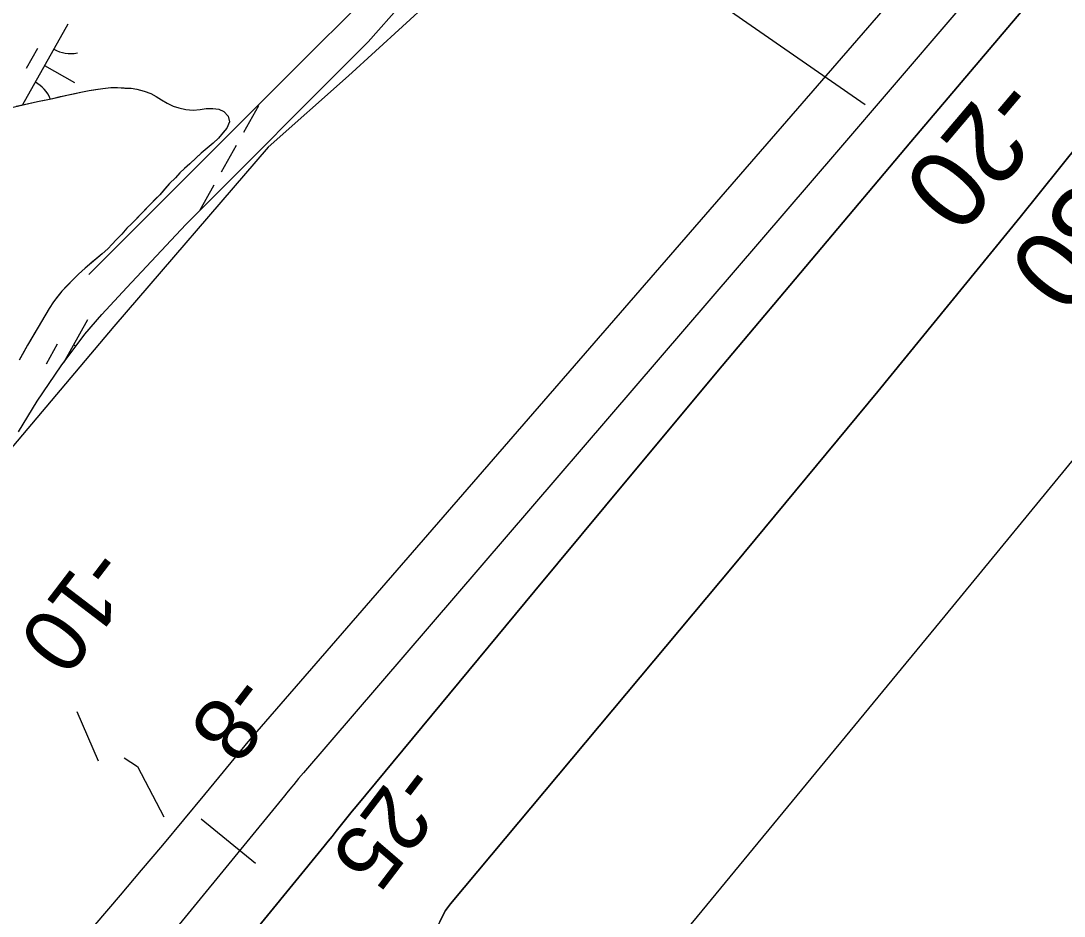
# Model space of a CAD drawing. Extents: x 3913936 to 3933962, y 195330 to 217741.
# Drawn here: x 3920751 to 3921301, y 199907 to 200379 of the extents above; entities that cross this region are included whole.
import ezdxf

# ---------------------------------------------------------------- set-up
doc = ezdxf.new("R2010")
doc.units = 0
for name, color, linetype in [('V-LEVE-TOET', 7, 'Continuous'), ('V-RIVR-EDGE', 7, 'Continuous'), ('V-RIVR-RANG', 7, 'Continuous'), ('V-RRAP-FSHR', 7, 'Continuous'), ('V-TOPO-DPTH', 7, 'Continuous'), ('V-TOPO-MINR', 7, 'Continuous'), ('V-TOPO-MINR-IDEN', 7, 'Continuous'), ('V-TOPO-SHOR', 7, 'Continuous'), ('V-WETL-SWMP', 7, 'Continuous')]:
    doc.layers.add(name, color=color, linetype=linetype)

msp = doc.modelspace()

# ---------------------------------------------------------------- linework, layer by layer
at = {"layer": 'V-LEVE-TOET'}
for p, q in [((3921120.69, 200387.67), (3921196.16, 200335.19)), ((3920780.73, 200015.29), (3920791.94, 199989.35)), ((3920846.19, 199958.71), (3920874.83, 199935.41))]:
    msp.add_line(p, q, dxfattribs=at)
msp.add_lwpolyline([(3920805.66, 199990.88), (3920812.72, 199986.44), (3920826.52, 199959.76)], dxfattribs=at)
at = {"layer": 'V-RIVR-EDGE'}
msp.add_lwpolyline([(3921670.35, 201179.41), (3921549.12, 201020.46), (3921415.83, 200875.05), (3921337.06, 200789.01), (3921188.01, 200632.69), (3921116.52, 200553.92), (3921101.97, 200528.48), (3921075.31, 200490.91), (3921049.87, 200450.92), (3921013.51, 200416.99), (3920980.8, 200402.45), (3920923.84, 200350.34), (3920881.43, 200312.78), (3920800.24, 200218.26), (3920726.32, 200131.01), (3920696.03, 200086.18), (3920643.92, 200055.88), (3920594.24, 200014.68), (3920561.69, 199977.31)], dxfattribs=at)
at = {"layer": 'V-RRAP-FSHR'}
msp.add_lwpolyline([(3921316.26, 200790.85), (3921288.87, 200761.7), (3921261.48, 200732.55), (3921234.92, 200703.4), (3921206.7, 200674.25), (3921179.24, 200645.17), (3921151.59, 200616.25), (3921123.95, 200587.34), (3921096.31, 200558.43), (3921068.67, 200529.52), (3921041.3, 200500.6), (3921013.29, 200471.79), (3920984.99, 200443.51), (3920956.7, 200415.24), (3920928.4, 200386.97), (3920900.1, 200358.7), (3920871.81, 200330.43), (3920843.51, 200302.15), (3920815.21, 200273.88), (3920786.92, 200245.61)], dxfattribs=at)
at = {"layer": 'V-TOPO-DPTH'}
for points in [[(3920788.48, 199794.34), (3920911.1, 199944.31), (3920913.22, 199946.93), (3920915.33, 199949.55), (3920917.43, 199952.19), (3920919.51, 199954.83), (3920921.59, 199957.48), (3920923.69, 199960.11), (3920925.82, 199962.73), (3920927.95, 199965.33), (3921022.08, 200078.98), (3921071.39, 200138.31), (3921120.84, 200197.54), (3921170.49, 200256.59), (3921220.27, 200315.53), (3921558.35, 200714.44)], [(3920788.48, 199794.34), (3920911.1, 199944.31), (3920913.22, 199946.93), (3920915.33, 199949.55), (3920917.43, 199952.19), (3920919.51, 199954.83), (3920921.59, 199957.48), (3920923.69, 199960.11), (3920925.82, 199962.73), (3920927.95, 199965.33), (3921022.08, 200078.98), (3921071.39, 200138.31), (3921120.84, 200197.54), (3921170.49, 200256.59), (3921220.27, 200315.53), (3921558.35, 200714.44)], [(3921471.9, 200692.25), (3920871.94, 200000.8), (3920869.85, 199998.3), (3920869.16, 199997.46), (3920847.89, 199971.56), (3920836.87, 199958.21), (3920825.8, 199944.92), (3920814.65, 199931.69), (3920803.45, 199918.5), (3920734.51, 199837.88)], [(3921352.15, 200368.45), (3921277.9, 200275.87), (3921202.76, 200184.01), (3921127.03, 200092.63), (3920977.56, 199914.02), (3920974.94, 199910.42), (3920973.84, 199908.49), (3920971.91, 199904.46), (3920970.96, 199902.43), (3920969, 199898.4), (3920967.88, 199896.34), (3920966.71, 199894.4), (3920964.02, 199890.75), (3920850.02, 199744.69)], [(3920850.02, 199744.69), (3920964.02, 199890.75), (3920966.71, 199894.4), (3920967.88, 199896.34), (3920969, 199898.4), (3920970.96, 199902.43), (3920971.91, 199904.46), (3920973.84, 199908.49), (3920974.94, 199910.42), (3920977.56, 199914.02), (3921127.03, 200092.63), (3921202.76, 200184.01), (3921277.9, 200275.87), (3921352.15, 200368.45)], [(3921311.35, 200154.93), (3921238.07, 200065.8), (3921049.22, 199836.48), (3921047.87, 199834.83), (3921045.18, 199831.52), (3921043.85, 199829.86), (3921041.19, 199826.53), (3921039.87, 199824.86), (3921038.56, 199823.18), (3920928.23, 199681.59)], [(3921311.35, 200154.93), (3921238.07, 200065.8), (3921049.22, 199836.48), (3921047.87, 199834.83), (3921045.18, 199831.52), (3921043.85, 199829.86), (3921041.19, 199826.53), (3921039.87, 199824.86), (3921038.56, 199823.18), (3920928.23, 199681.59)]]:
    msp.add_lwpolyline(points, dxfattribs=at)
at = {"layer": 'V-TOPO-MINR'}
for points in [[(3921558.35, 200714.44), (3921220.27, 200315.53), (3921170.49, 200256.59), (3921120.84, 200197.54), (3921071.39, 200138.31), (3921022.08, 200078.98), (3920927.95, 199965.33), (3920925.82, 199962.73), (3920923.69, 199960.11), (3920921.59, 199957.48), (3920919.51, 199954.83), (3920917.43, 199952.19), (3920915.33, 199949.55), (3920913.22, 199946.93), (3920911.1, 199944.31), (3920788.48, 199794.34)], [(3921471.9, 200692.25), (3920871.94, 200000.8), (3920869.85, 199998.3), (3920869.16, 199997.46), (3920847.89, 199971.56), (3920836.87, 199958.21), (3920825.8, 199944.92), (3920814.65, 199931.69), (3920803.45, 199918.5), (3920734.51, 199837.88)], [(3921302.59, 200452.29), (3921241.83, 200381.14), (3921180.96, 200310.09), (3920900.1, 199982.95), (3920897.57, 199979.97), (3920895.08, 199976.95), (3920893.84, 199975.43), (3920891.36, 199972.4), (3920890.13, 199970.89), (3920813.14, 199876.93), (3920773.5, 199828.36), (3920762.73, 199815.11)], [(3921352.15, 200368.45), (3921277.9, 200275.87), (3921202.76, 200184.01), (3921127.03, 200092.63), (3920977.56, 199914.02), (3920974.94, 199910.42), (3920973.84, 199908.49), (3920971.91, 199904.46), (3920970.96, 199902.43), (3920969, 199898.4), (3920967.88, 199896.34), (3920966.71, 199894.4), (3920964.02, 199890.75), (3920850.02, 199744.69)], [(3921311.35, 200154.93), (3921238.07, 200065.8), (3921049.22, 199836.48), (3921047.87, 199834.83), (3921045.18, 199831.52), (3921043.85, 199829.86), (3921041.19, 199826.53), (3921039.87, 199824.86), (3921038.56, 199823.18), (3920928.23, 199681.59)]]:
    msp.add_lwpolyline(points, dxfattribs=at)
at = {"layer": 'V-TOPO-SHOR'}
msp.add_lwpolyline([(3920748.67, 200334.3), (3920752.03, 200335.05), (3920756.76, 200336.06), (3920759.99, 200336.82), (3920763.6, 200337.57), (3920767.96, 200338.46), (3920772.06, 200339.46), (3920775.42, 200340.22), (3920779.77, 200341.1), (3920782.75, 200341.73), (3920787.23, 200342.62), (3920790.59, 200343.12), (3920794.45, 200343.76), (3920798.68, 200344.14), (3920802.04, 200344.15), (3920806.02, 200343.92), (3920809.26, 200343.8), (3920812.37, 200343.31), (3920816.11, 200342.2), (3920819.72, 200340.97), (3920822.47, 200339.48), (3920825.33, 200337.62), (3920828.33, 200335.89), (3920831.44, 200334.4), (3920834.43, 200333.42), (3920838.04, 200332.55), (3920842.03, 200332.32), (3920845.64, 200332.58), (3920848.87, 200333.08), (3920852.35, 200333.22), (3920855.47, 200332.73), (3920858.21, 200331.49), (3920860.46, 200329.13), (3920861.21, 200326.15), (3920859.73, 200322.78), (3920857.62, 200320.29), (3920855.26, 200317.54), (3920852.53, 200314.92), (3920849.3, 200312.17), (3920846.2, 200309.55), (3920843.84, 200307.43), (3920840.24, 200304.06), (3920837.38, 200301.56), (3920835.02, 200299.19), (3920832.67, 200296.57), (3920829.56, 200293.57), (3920826.83, 200290.58), (3920824.35, 200287.71), (3920822, 200285.34), (3920819.64, 200282.96), (3920817.4, 200280.59), (3920815.17, 200278.1), (3920811.69, 200274.61), (3920809.46, 200272.36), (3920806.98, 200270.11), (3920804.37, 200266.99), (3920801.39, 200264), (3920799.29, 200261.62), (3920796.93, 200259.26), (3920794.07, 200256.63), (3920790.84, 200253.89), (3920788.11, 200251.64), (3920785.01, 200249.02), (3920781.53, 200245.89), (3920778.55, 200242.9), (3920775.32, 200239.65), (3920772.72, 200236.91), (3920770.73, 200234.29), (3920768.38, 200231.29), (3920766.02, 200227.68), (3920763.79, 200223.81), (3920762.06, 200220.82), (3920760.32, 200217.83), (3920758.22, 200214.46), (3920756.73, 200211.85), (3920754.62, 200208.48), (3920752.52, 200204.49), (3920750.29, 200200.5)], dxfattribs=at)
at = {"layer": 'V-WETL-SWMP'}
for p, q in [((3920934.27, 200368.24), (3920951.97, 200388.35)), ((3920775.96, 200377.52), (3920752.06, 200335.02)), ((3920838.05, 200271.99), (3920934.27, 200368.24)), ((3920759.92, 200364.73), (3920754.04, 200354.27)), ((3920763.7, 200355.72), (3920779.4, 200346.9)), ((3920767.95, 200338.46), (3920775.42, 200340.22)), ((3920775.42, 200340.22), (3920782.76, 200341.73)), ((3920782.76, 200341.73), (3920787.23, 200342.62)), ((3920787.23, 200342.62), (3920794.45, 200343.76)), ((3920794.45, 200343.76), (3920798.68, 200344.14)), ((3920798.68, 200344.14), (3920802.04, 200344.15)), ((3920802.04, 200344.15), (3920809.26, 200343.8)), ((3920809.26, 200343.8), (3920812.37, 200343.31)), ((3920812.37, 200343.31), (3920816.11, 200342.2)), ((3920816.11, 200342.2), (3920819.72, 200340.97)), ((3920819.72, 200340.97), (3920822.47, 200339.48)), ((3920745.56, 200333.54), (3920759.99, 200336.82)), ((3920759.99, 200336.82), (3920767.95, 200338.46)), ((3920822.47, 200339.48), (3920825.33, 200337.62)), ((3920825.33, 200337.62), (3920828.33, 200335.89)), ((3920828.33, 200335.89), (3920831.44, 200334.4)), ((3920831.44, 200334.4), (3920834.43, 200333.42)), ((3920834.43, 200333.42), (3920838.04, 200332.55)), ((3920838.04, 200332.55), (3920842.03, 200332.32)), ((3920842.03, 200332.32), (3920845.64, 200332.58)), ((3920845.64, 200332.58), (3920848.87, 200333.08)), ((3920848.87, 200333.08), (3920852.35, 200333.22)), ((3920852.35, 200333.22), (3920855.47, 200332.73)), ((3920855.47, 200332.73), (3920858.21, 200331.49)), ((3920858.21, 200331.49), (3920860.46, 200329.13)), ((3920860.46, 200329.13), (3920861.21, 200326.15)), ((3920876.38, 200334.49), (3920868.54, 200320.54)), ((3920861.21, 200326.15), (3920859.73, 200322.78)), ((3920859.73, 200322.78), (3920855.26, 200317.54)), ((3920852.53, 200314.92), (3920846.2, 200309.55)), ((3920855.26, 200317.54), (3920852.53, 200314.92)), ((3920864.62, 200313.57), (3920856.78, 200299.62)), ((3920846.2, 200309.55), (3920840.24, 200304.06)), ((3920840.24, 200304.06), (3920837.38, 200301.56)), ((3920832.67, 200296.57), (3920829.56, 200293.57)), ((3920835.02, 200299.19), (3920832.67, 200296.57)), ((3920837.38, 200301.56), (3920835.02, 200299.19)), ((3920829.56, 200293.57), (3920824.35, 200287.71)), ((3920852.86, 200292.65), (3920845.35, 200279.29)), ((3920824.35, 200287.71), (3920819.64, 200282.96)), ((3920819.64, 200282.96), (3920815.17, 200278.1)), ((3920815.17, 200278.1), (3920809.46, 200272.36)), ((3920806.98, 200270.11), (3920804.37, 200266.99)), ((3920809.46, 200272.36), (3920806.98, 200270.11)), ((3920807.01, 200238.72), (3920838.05, 200271.99)), ((3920801.39, 200264), (3920799.28, 200261.62)), ((3920804.37, 200266.99), (3920801.39, 200264)), ((3920796.93, 200259.25), (3920794.07, 200256.63)), ((3920799.28, 200261.62), (3920796.93, 200259.25)), ((3920794.07, 200256.63), (3920785.01, 200249.02)), ((3920785.01, 200249.02), (3920781.53, 200245.89)), ((3920781.53, 200245.89), (3920772.72, 200236.91)), ((3920772.72, 200236.91), (3920768.38, 200231.29)), ((3920793.93, 200224.53), (3920807.01, 200238.72)), ((3920768.38, 200231.29), (3920766.02, 200227.68)), ((3920766.02, 200227.68), (3920760.32, 200217.83)), ((3920786.35, 200221.72), (3920773.67, 200199.16)), ((3920784.95, 200214.21), (3920793.93, 200224.53)), ((3920760.32, 200217.83), (3920754.62, 200208.48)), ((3920772.39, 200197.45), (3920784.95, 200214.21)), ((3920754.62, 200208.48), (3920750.29, 200200.5)), ((3920770.31, 200208.94), (3920764.43, 200198.47)), ((3920759.83, 200178.89), (3920772.39, 200197.45)), ((3920774.1, 200199.92), (3920774.2, 200199.87)), ((3920749.85, 200162.65), (3920759.83, 200178.89))]:
    msp.add_line(p, q, dxfattribs=at)
for centre, start, end in [((3920777.45, 200379.68), 239.8861, 281.4297), ((3920750.38, 200331.53), 22.2305, 61.4297), ((3920787.84, 200223.89), 239.8861, 244.5689)]:
    msp.add_arc(centre, 17.62, start, end, dxfattribs=at)

# ---------------------------------------------------------------- texts
at = {"layer": 'V-RIVR-RANG'}
for s, p in [('-10', (3920788.02, 200104.33)), ('-8', (3920862.93, 200037.65)), ('-25', (3920952.64, 199990.36))]:
    msp.add_text(s, height=33.5, rotation=232.6283, dxfattribs=at).set_placement(p)
at = {"layer": 'V-TOPO-MINR-IDEN'}
for s, rotation, p in [('-20', 229.7181, (3921265.9, 200353.33)), ('-30', 231.2709, (3921319.93, 200311.7))]:
    msp.add_text(s, height=41.5, rotation=rotation, dxfattribs=at).set_placement(p)

doc.saveas('drawing.dxf')
